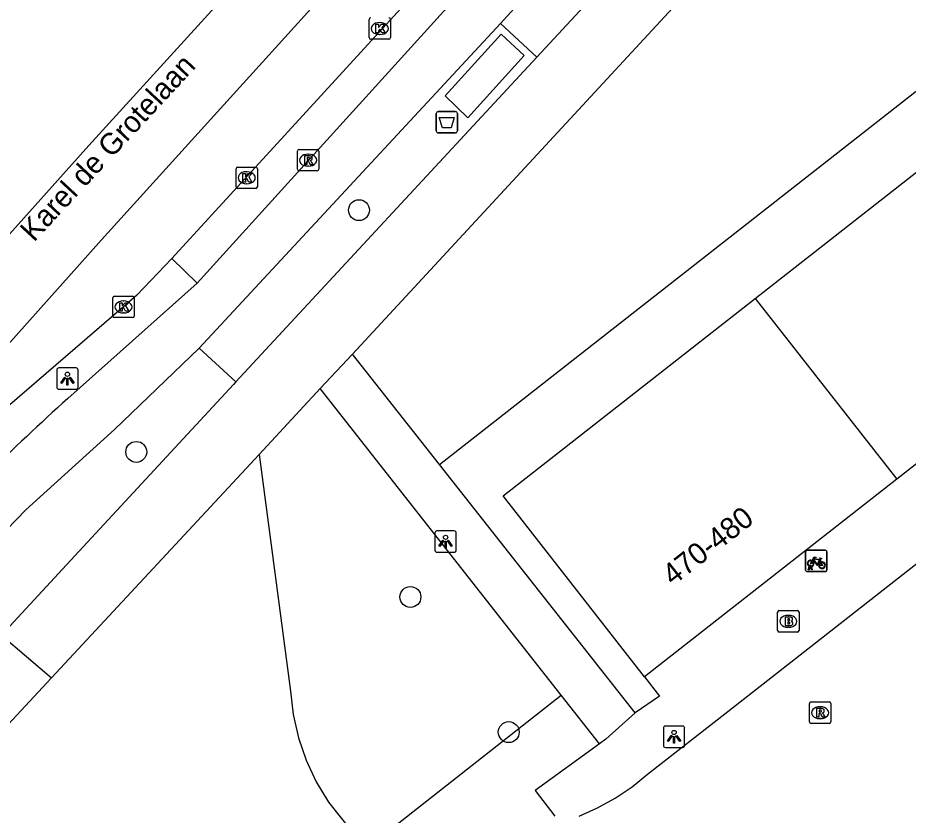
# Model space of a CAD drawing. Extents: x 159222 to 160346, y 381249 to 382166.
# Drawn here: x 159605.34 to 159647.03, y 381597.22 to 381634.54 of the extents above; entities that cross this region are included whole.
import ezdxf

# ---------------------------------------------------------------- set-up
doc = ezdxf.new("R2010")
doc.units = 0
for name, color, linetype in [('IMGEO_Afvalbak', 7, 'Continuous'), ('IMGEO_Boom', 7, 'Continuous'), ('IMGEO_Brandkraan', 7, 'Continuous'), ('IMGEO_Fietsenrek', 7, 'Continuous'), ('IMGEO_Fietspad_gesloten', 7, 'Continuous'), ('IMGEO_Groenvoorziening', 7, 'Continuous'), ('IMGEO_Kolk', 7, 'Continuous'), ('IMGEO_Lichtpunt', 7, 'Continuous'), ('IMGEO_Openbare_ruimte_label', 7, 'Continuous'), ('IMGEO_OVBaan_gesloten', 7, 'Continuous'), ('IMGEO_Pand', 7, 'Continuous'), ('IMGEO_Pand_nummerreeks', 7, 'Continuous'), ('IMGEO_Rijbaan_lokaal_open', 7, 'Continuous'), ('IMGEO_Rijbaan_regionaal_gesloten', 7, 'Continuous'), ('IMGEO_Rioolput', 7, 'Continuous'), ('IMGEO_Voetpad_gesloten', 7, 'Continuous'), ('IMGEO_Voetpad_open', 7, 'Continuous')]:
    doc.layers.add(name, color=color, linetype=linetype)

msp = doc.modelspace()

# ---------------------------------------------------------------- linework, layer by layer
at = {"layer": 'IMGEO_Afvalbak'}
for p, q in [((159625.031, 381630.153), (159625.821, 381630.153)), ((159625.821, 381630.153), (159625.031, 381630.153)), ((159624.931, 381629.253), (159624.931, 381630.053)), ((159624.931, 381630.053), (159624.931, 381629.253)), ((159625.921, 381630.053), (159625.921, 381629.253)), ((159625.921, 381629.253), (159625.921, 381630.053)), ((159625.821, 381629.153), (159625.031, 381629.153)), ((159625.031, 381629.153), (159625.821, 381629.153))]:
    msp.add_line(p, q, dxfattribs=at)
msp.add_lwpolyline([(159625.074, 381629.867), (159625.778, 381629.867), (159625.629, 381629.397), (159625.223, 381629.397), (159625.074, 381629.867)], dxfattribs=at)
for centre, start, end in [((159625.031, 381630.053), 90, 180), ((159625.031, 381630.053), 90, 180), ((159625.821, 381630.053), 0, 90), ((159625.821, 381630.053), 360, 90), ((159625.031, 381629.253), 180, 270), ((159625.031, 381629.253), 180, 270), ((159625.821, 381629.253), 270, 0), ((159625.821, 381629.253), 270, 0)]:
    msp.add_arc(centre, 0.1, start, end, dxfattribs=at)
at = {"layer": 'IMGEO_Boom'}
for centre in [(159621.315, 381625.537), (159610.887, 381614.222), (159623.723, 381607.432), (159628.329, 381601.108)]:
    msp.add_circle(centre, 0.489, dxfattribs=at)
at = {"layer": 'IMGEO_Brandkraan'}
for p, q in [((159640.919, 381605.866), (159640.919, 381606.718)), ((159640.994, 381606.792), (159641.846, 381606.792)), ((159641.92, 381606.718), (159641.92, 381605.866)), ((159641.407, 381606.572), (159641.432, 381606.572)), ((159641.43, 381606.012), (159641.405, 381606.012)), ((159641.846, 381605.792), (159640.994, 381605.792))]:
    msp.add_line(p, q, dxfattribs=at)
for points in [[(159640.919, 381605.866), (159640.919, 381606.718)], [(159640.994, 381606.792), (159641.846, 381606.792)], [(159641.92, 381606.718), (159641.92, 381605.866)], [(159641.267, 381606.492), (159641.267, 381606.092), (159641.48, 381606.092)], [(159641.498, 381606.492), (159641.267, 381606.492)], [(159641.446, 381606.411), (159641.392, 381606.411), (159641.392, 381606.335)], [(159641.392, 381606.335), (159641.445, 381606.335)], [(159641.454, 381606.259), (159641.392, 381606.259), (159641.392, 381606.178)], [(159641.392, 381606.178), (159641.454, 381606.178)], [(159641.846, 381605.792), (159640.994, 381605.792)]]:
    msp.add_lwpolyline(points, dxfattribs=at)
for centre, radius, start, end in [((159640.996, 381606.716), 0.0765, 91.552, 178.448), ((159640.996, 381606.716), 0.0765, 91.552, 178.448), ((159641.844, 381606.716), 0.0765, 1.552, 88.448), ((159641.844, 381606.716), 0.0765, 1.552, 88.448), ((159641.447, 381606.373), 0.0379, 267.8285, 90.9355), ((159641.502, 381606.347), 0.145, 59.4692, 91.5367), ((159641.527, 381606.394), 0.0922, 285.5137, 58.1501), ((159641.532, 381606.202), 0.105, 301.3115, 78.989), ((159641.455, 381606.218), 0.0404, 269.8759, 90.5077), ((159641.486, 381606.343), 0.251, 268.6676, 293.5347), ((159640.996, 381605.868), 0.0765, 181.552, 268.448), ((159640.996, 381605.868), 0.0765, 181.552, 268.448), ((159641.844, 381605.868), 0.0765, 271.552, 358.448), ((159641.844, 381605.868), 0.0765, 271.552, 358.448)]:
    msp.add_arc(centre, radius, start, end, dxfattribs=at)
for centre, major_axis, ratio, start_param, end_param in [((159641.406, 381606.292), (-0.387, 0.002), 0.722429, 4.712389, 7.853982), ((159641.431, 381606.292), (-0.39, 0.002), 0.717154, 1.570796, 4.712389)]:
    msp.add_ellipse(centre, major_axis=major_axis, ratio=ratio, start_param=start_param, end_param=end_param, dxfattribs=at)
at = {"layer": 'IMGEO_Fietsenrek'}
for p, q in [((159642.228, 381608.692), (159642.228, 381609.533)), ((159642.228, 381609.533), (159642.228, 381608.692)), ((159642.303, 381609.617), (159643.144, 381609.617)), ((159643.144, 381609.617), (159642.303, 381609.617)), ((159643.228, 381609.542), (159643.228, 381608.701)), ((159643.228, 381608.701), (159643.228, 381609.542)), ((159642.355, 381608.701), (159642.394, 381608.861)), ((159642.424, 381608.849), (159642.389, 381608.701)), ((159642.466, 381608.873), (159642.465, 381608.877)), ((159642.507, 381608.701), (159642.473, 381608.843)), ((159642.497, 381608.884), (159642.498, 381608.877)), ((159642.505, 381608.847), (159642.54, 381608.701)), ((159642.915, 381609.166), (159642.951, 381609.071)), ((159643.153, 381608.617), (159642.312, 381608.617)), ((159642.312, 381608.617), (159643.153, 381608.617)), ((159642.389, 381608.701), (159642.355, 381608.701)), ((159642.54, 381608.701), (159642.507, 381608.701))]:
    msp.add_line(p, q, dxfattribs=at)
for points in [[(159642.541, 381609.143), (159642.636, 381609.307), (159642.722, 381609.293), (159642.724, 381609.284), (159642.668, 381609.273), (159642.641, 381609.228), (159642.897, 381609.187)], [(159642.897, 381609.187), (159642.922, 381609.236), (159642.916, 381609.24), (159642.893, 381609.244), (159642.881, 381609.251), (159642.88, 381609.254), (159642.882, 381609.259), (159642.977, 381609.244), (159642.979, 381609.234), (159642.969, 381609.221), (159642.957, 381609.215), (159642.943, 381609.221), (159642.915, 381609.166)], [(159642.562, 381609.091), (159642.51, 381609.001), (159642.47, 381608.976), (159642.471, 381609.023), (159642.526, 381609.117)], [(159642.837, 381608.899), (159642.787, 381608.899), (159642.596, 381609.15), (159642.577, 381609.118)], [(159642.884, 381609.162), (159642.627, 381609.203), (159642.61, 381609.174), (159642.777, 381608.954), (159642.884, 381609.162)], [(159642.932, 381609.064), (159642.902, 381609.141), (159642.793, 381608.923), (159642.836, 381608.923)], [(159642.866, 381608.923), (159642.986, 381608.922), (159642.942, 381609.036)], [(159642.962, 381609.043), (159643.017, 381608.898), (159642.867, 381608.898)]]:
    msp.add_lwpolyline(points, dxfattribs=at)
for centre, radius, start, end in [((159642.306, 381609.539), 0.0779, 92.4484, 184.2845), ((159642.306, 381609.539), 0.0779, 92.4484, 184.2845), ((159643.15, 381609.539), 0.0779, 2.4484, 94.2845), ((159643.15, 381609.539), 0.0779, 2.4484, 94.2845), ((159642.468, 381609.002), 0.159, 62.6766, 242.1369), ((159642.468, 381609.002), 0.129, 63.3192, 238.903), ((159642.448, 381608.873), 0.0499, 12.8025, 158.6934), ((159642.468, 381609.002), 0.159, 253.9967, 271.7867), ((159642.448, 381608.873), 0.0174, 12.8025, 163.4502), ((159642.468, 381609.002), 0.129, 253.415, 269.0204), ((159642.468, 381609.002), 0.129, 283.6043, 43.4302), ((159642.468, 381609.002), 0.159, 283.5766, 46.6042), ((159642.995, 381608.918), 0.159, 113.3408, 178.3217), ((159642.995, 381608.918), 0.159, 187.0065, 105.7708), ((159642.995, 381608.918), 0.129, 113.923, 177.9556), ((159642.995, 381608.918), 0.129, 188.6715, 104.5883), ((159642.306, 381608.695), 0.0779, 182.4484, 274.2845), ((159642.306, 381608.695), 0.0779, 182.4484, 274.2845), ((159643.15, 381608.695), 0.0779, 272.4484, 4.2845), ((159643.15, 381608.695), 0.0779, 272.4484, 4.2845)]:
    msp.add_arc(centre, radius, start, end, dxfattribs=at)
at = {"layer": 'IMGEO_Fietspad_gesloten'}
for points in [[(159627.95, 381634.279), (159632.567, 381639.362), (159637.494, 381645.52), (159642.695, 381651.795), (159649.844, 381659.632), (159712.278, 381726.997), (159749.294, 381767.255), (159766.48, 381785.868)], [(159629.68, 381639.699), (159613.744, 381622.115)], [(159627.95, 381634.279), (159613.837, 381619.072)], [(159613.744, 381622.115), (159607.679, 381616.725)], [(159602.096, 381607.781), (159605.72, 381611.514), (159609.864, 381615.275), (159613.837, 381619.072)]]:
    msp.add_lwpolyline(points, dxfattribs=at)
msp.add_arc((159701.931, 381512.769), 140.322, 132.19716, 136.47098, dxfattribs=at)
at = {"layer": 'IMGEO_Groenvoorziening'}
for points in [[(159625.084, 381613.639), (159671.617, 381650.084)], [(159616.639, 381614.101), (159618.108, 381603.028), (159618.241, 381601.924), (159618.489, 381600.841), (159618.848, 381599.789), (159619.316, 381598.78), (159619.886, 381597.826), (159620.974, 381596.463), (159621.716, 381595.714)], [(159621.716, 381595.714), (159630.786, 381602.842)]]:
    msp.add_lwpolyline(points, dxfattribs=at)
at = {"layer": 'IMGEO_Kolk'}
for p, q in [((159621.789, 381633.612), (159621.789, 381634.464)), ((159622.277, 381634.318), (159622.302, 381634.318)), ((159622.79, 381634.464), (159622.79, 381633.612)), ((159622.716, 381633.538), (159621.864, 381633.538)), ((159622.3, 381633.758), (159622.275, 381633.758)), ((159615.558, 381626.626), (159615.558, 381627.478)), ((159615.633, 381627.552), (159616.485, 381627.552)), ((159616.046, 381627.332), (159616.071, 381627.332)), ((159616.559, 381627.478), (159616.559, 381626.626)), ((159616.069, 381626.772), (159616.044, 381626.772)), ((159616.485, 381626.552), (159615.633, 381626.552)), ((159609.789, 381620.58), (159609.789, 381621.432)), ((159609.864, 381621.506), (159610.716, 381621.506)), ((159610.79, 381621.432), (159610.79, 381620.58)), ((159610.277, 381621.286), (159610.302, 381621.286)), ((159610.716, 381620.506), (159609.864, 381620.506)), ((159610.3, 381620.726), (159610.275, 381620.726))]:
    msp.add_line(p, q, dxfattribs=at)
for points in [[(159621.789, 381633.612), (159621.789, 381634.464)], [(159622.11, 381634.238), (159622.233, 381634.238), (159622.233, 381634.087), (159622.363, 381634.238), (159622.527, 381634.238), (159622.381, 381634.087), (159622.534, 381633.838), (159622.382, 381633.838), (159622.297, 381634.002), (159622.233, 381633.935), (159622.233, 381633.838), (159622.11, 381633.838), (159622.11, 381634.238)], [(159622.79, 381634.464), (159622.79, 381633.612)], [(159622.716, 381633.538), (159621.864, 381633.538)], [(159615.558, 381626.626), (159615.558, 381627.478)], [(159615.633, 381627.552), (159616.485, 381627.552)], [(159615.879, 381627.252), (159616.002, 381627.252), (159616.002, 381627.101), (159616.132, 381627.252), (159616.296, 381627.252), (159616.15, 381627.101), (159616.303, 381626.852), (159616.151, 381626.852), (159616.066, 381627.016), (159616.002, 381626.949), (159616.002, 381626.852), (159615.879, 381626.852), (159615.879, 381627.252)], [(159616.559, 381627.478), (159616.559, 381626.626)], [(159616.485, 381626.552), (159615.633, 381626.552)], [(159609.789, 381620.58), (159609.789, 381621.432)], [(159609.864, 381621.506), (159610.716, 381621.506)], [(159610.79, 381621.432), (159610.79, 381620.58)], [(159610.11, 381621.206), (159610.233, 381621.206), (159610.233, 381621.055), (159610.363, 381621.206), (159610.527, 381621.206), (159610.381, 381621.055), (159610.534, 381620.806), (159610.382, 381620.806), (159610.297, 381620.97), (159610.233, 381620.903), (159610.233, 381620.806), (159610.11, 381620.806), (159610.11, 381621.206)], [(159610.716, 381620.506), (159609.864, 381620.506)]]:
    msp.add_lwpolyline(points, dxfattribs=at)
for centre, start, end in [((159621.866, 381634.462), 91.552, 178.448), ((159621.866, 381634.462), 91.552, 178.448), ((159622.714, 381634.462), 1.552, 88.448), ((159622.714, 381634.462), 1.552, 88.448), ((159621.866, 381633.614), 181.552, 268.448), ((159621.866, 381633.614), 181.552, 268.448), ((159622.714, 381633.614), 271.552, 358.448), ((159622.714, 381633.614), 271.552, 358.448), ((159615.635, 381627.476), 91.552, 178.448), ((159615.635, 381627.476), 91.552, 178.448), ((159616.483, 381627.476), 1.552, 88.448), ((159616.483, 381627.476), 1.552, 88.448), ((159615.635, 381626.628), 181.552, 268.448), ((159615.635, 381626.628), 181.552, 268.448), ((159616.483, 381626.628), 271.552, 358.448), ((159616.483, 381626.628), 271.552, 358.448), ((159609.866, 381621.43), 91.552, 178.448), ((159609.866, 381621.43), 91.552, 178.448), ((159610.714, 381621.43), 1.552, 88.448), ((159610.714, 381621.43), 1.552, 88.448), ((159609.866, 381620.582), 181.552, 268.448), ((159609.866, 381620.582), 181.552, 268.448), ((159610.714, 381620.582), 271.552, 358.448), ((159610.714, 381620.582), 271.552, 358.448)]:
    msp.add_arc(centre, 0.0765, start, end, dxfattribs=at)
for centre, major_axis, ratio, start_param, end_param in [((159622.276, 381634.038), (-0.387, 0.002), 0.722429, 4.712389, 7.853982), ((159622.301, 381634.038), (-0.39, 0.002), 0.717154, 1.570796, 4.712389), ((159616.045, 381627.052), (-0.387, 0.002), 0.722429, 4.712389, 7.853982), ((159616.07, 381627.052), (-0.39, 0.002), 0.717154, 1.570796, 4.712389), ((159610.276, 381621.006), (-0.387, 0.002), 0.722429, 4.712389, 7.853982), ((159610.301, 381621.006), (-0.39, 0.002), 0.717154, 1.570796, 4.712389)]:
    msp.add_ellipse(centre, major_axis=major_axis, ratio=ratio, start_param=start_param, end_param=end_param, dxfattribs=at)
at = {"layer": 'IMGEO_Lichtpunt'}
for p, q in [((159607.165, 381618.057), (159607.165, 381617.25)), ((159607.165, 381618.057), (159607.165, 381617.25)), ((159608.067, 381618.152), (159607.259, 381618.152)), ((159608.067, 381618.152), (159607.259, 381618.152)), ((159608.161, 381617.25), (159608.161, 381618.057)), ((159608.161, 381617.25), (159608.161, 381618.057)), ((159607.259, 381617.156), (159608.067, 381617.156)), ((159607.259, 381617.156), (159608.067, 381617.156)), ((159625.775, 381610.522), (159624.967, 381610.522)), ((159625.775, 381610.522), (159624.967, 381610.522)), ((159624.873, 381610.427), (159624.873, 381609.62)), ((159624.873, 381610.427), (159624.873, 381609.62)), ((159625.869, 381609.62), (159625.869, 381610.427)), ((159625.869, 381609.62), (159625.869, 381610.427)), ((159624.967, 381609.526), (159625.775, 381609.526)), ((159624.967, 381609.526), (159625.775, 381609.526)), ((159635.57, 381601.293), (159635.57, 381600.486)), ((159635.57, 381601.293), (159635.57, 381600.486)), ((159636.472, 381601.388), (159635.664, 381601.388)), ((159636.472, 381601.388), (159635.664, 381601.388)), ((159636.566, 381600.486), (159636.566, 381601.293)), ((159636.566, 381600.486), (159636.566, 381601.293)), ((159635.664, 381600.392), (159636.472, 381600.392)), ((159635.664, 381600.392), (159636.472, 381600.392))]:
    msp.add_line(p, q, dxfattribs=at)
for points in [[(159607.539, 381617.721), (159607.578, 381617.693), (159607.39, 381617.431), (159607.352, 381617.458), (159607.539, 381617.721)], [(159607.641, 381617.673), (159607.688, 381617.673), (159607.688, 381617.351), (159607.641, 381617.351), (159607.641, 381617.673)], [(159607.751, 381617.693), (159607.789, 381617.72), (159607.976, 381617.458), (159607.937, 381617.43), (159607.751, 381617.693)], [(159625.247, 381610.091), (159625.286, 381610.063), (159625.098, 381609.801), (159625.06, 381609.828), (159625.247, 381610.091)], [(159625.349, 381610.043), (159625.396, 381610.043), (159625.396, 381609.721), (159625.349, 381609.721), (159625.349, 381610.043)], [(159625.459, 381610.063), (159625.497, 381610.09), (159625.684, 381609.828), (159625.645, 381609.8), (159625.459, 381610.063)], [(159635.944, 381600.957), (159635.983, 381600.929), (159635.795, 381600.667), (159635.757, 381600.694), (159635.944, 381600.957)], [(159636.046, 381600.909), (159636.093, 381600.909), (159636.093, 381600.587), (159636.046, 381600.587), (159636.046, 381600.909)], [(159636.156, 381600.929), (159636.194, 381600.956), (159636.381, 381600.694), (159636.342, 381600.666), (159636.156, 381600.929)]]:
    msp.add_lwpolyline(points, dxfattribs=at)
for centre in [(159607.664, 381617.855), (159625.372, 381610.225), (159636.069, 381601.091)]:
    msp.add_circle(centre, 0.0994, dxfattribs=at)
for centre, start, end in [((159607.259, 381618.057), 90, 180), ((159607.259, 381618.057), 90, 180), ((159608.067, 381618.057), 0, 90), ((159608.067, 381618.057), 0, 90), ((159607.259, 381617.25), 180, 270), ((159607.259, 381617.25), 180, 270), ((159608.067, 381617.25), 270, 0), ((159608.067, 381617.25), 270, 360), ((159624.967, 381610.427), 90, 180), ((159624.967, 381610.427), 90, 180), ((159625.775, 381610.427), 0, 90), ((159625.775, 381610.427), 0, 90), ((159624.967, 381609.62), 180, 270), ((159624.967, 381609.62), 180, 270), ((159625.775, 381609.62), 270, 0), ((159625.775, 381609.62), 270, 360), ((159635.664, 381601.293), 90, 180), ((159635.664, 381601.293), 90, 180), ((159636.472, 381601.293), 0, 90), ((159636.472, 381601.293), 0, 90), ((159635.664, 381600.486), 180, 270), ((159635.664, 381600.486), 180, 270), ((159636.472, 381600.486), 270, 0), ((159636.472, 381600.486), 270, 360)]:
    msp.add_arc(centre, 0.0946, start, end, dxfattribs=at)
at = {"layer": 'IMGEO_OVBaan_gesloten'}
for points in [[(159594.598, 381607.362), (159597.899, 381611.433), (159609.251, 381624.142), (159621.007, 381637.121), (159637.399, 381654.559)], [(159628.555, 381640.744), (159612.549, 381623.266)], [(159612.549, 381623.266), (159610.908, 381621.552), (159610.29, 381621.006), (159598.499, 381610.865), (159596.374, 381609.038), (159594.883, 381607.659), (159594.598, 381607.362)]]:
    msp.add_lwpolyline(points, dxfattribs=at)
at = {"layer": 'IMGEO_Pand'}
for points in [[(159639.869, 381621.408), (159651.678, 381630.657)], [(159658.311, 381622.189), (159646.502, 381612.939)], [(159634.693, 381603.69), (159628.06, 381612.159), (159639.869, 381621.408)], [(159639.869, 381621.408), (159646.502, 381612.939)], [(159646.502, 381612.939), (159634.693, 381603.69)]]:
    msp.add_lwpolyline(points, dxfattribs=at)
at = {"layer": 'IMGEO_Rijbaan_lokaal_open'}
msp.add_lwpolyline([(159631.625, 381597.172), (159632.49, 381597.556), (159633.318, 381598.016), (159634.101, 381598.548), (159634.829, 381599.144), (159638.593, 381602.067), (159674.232, 381629.981)], dxfattribs=at)
at = {"layer": 'IMGEO_Rijbaan_regionaal_gesloten'}
msp.add_lwpolyline([(159562.441, 381576.704), (159564.486, 381578.965), (159572.242, 381587.735), (159595.596, 381613.987), (159600.842, 381619.836), (159608.673, 381628.559), (159619.179, 381640.116), (159632.439, 381654.477), (159662.487, 381686.935), (159673.411, 381698.738), (159692.515, 381719.406), (159697.924, 381725.313), (159711.603, 381740.093), (159741.608, 381772.601), (159749.78, 381781.446), (159760.686, 381793.237), (159777.035, 381810.935), (159791.265, 381826.348), (159802.521, 381838.469), (159810.756, 381847.255), (159814.994, 381851.76)], dxfattribs=at)
at = {"layer": 'IMGEO_Rioolput'}
for p, q in [((159618.433, 381627.451), (159618.433, 381628.303)), ((159618.508, 381628.377), (159619.36, 381628.377)), ((159618.921, 381628.157), (159618.946, 381628.157)), ((159619.434, 381628.303), (159619.434, 381627.451)), ((159618.944, 381627.597), (159618.919, 381627.597)), ((159619.36, 381627.377), (159618.508, 381627.377)), ((159642.408, 381601.591), (159642.408, 381602.443)), ((159642.483, 381602.517), (159643.335, 381602.517)), ((159642.896, 381602.297), (159642.921, 381602.297)), ((159643.409, 381602.443), (159643.409, 381601.591)), ((159642.919, 381601.737), (159642.894, 381601.737)), ((159643.335, 381601.517), (159642.483, 381601.517))]:
    msp.add_line(p, q, dxfattribs=at)
for points in [[(159618.433, 381627.451), (159618.433, 381628.303)], [(159618.508, 381628.377), (159619.36, 381628.377)], [(159619.022, 381628.075), (159618.77, 381628.077), (159618.77, 381627.677)], [(159618.948, 381627.996), (159618.894, 381627.996), (159618.894, 381627.915)], [(159619.434, 381628.303), (159619.434, 381627.451)], [(159618.77, 381627.677), (159618.894, 381627.677), (159618.894, 381627.839), (159618.905, 381627.839)], [(159618.894, 381627.915), (159618.946, 381627.915)], [(159618.952, 381627.81), (159619.023, 381627.677), (159619.163, 381627.677), (159619.098, 381627.803)], [(159619.36, 381627.377), (159618.508, 381627.377)], [(159642.408, 381601.591), (159642.408, 381602.443)], [(159642.483, 381602.517), (159643.335, 381602.517)], [(159642.997, 381602.215), (159642.745, 381602.217), (159642.745, 381601.817)], [(159642.923, 381602.136), (159642.869, 381602.136), (159642.869, 381602.055)], [(159643.409, 381602.443), (159643.409, 381601.591)], [(159642.745, 381601.817), (159642.869, 381601.817), (159642.869, 381601.979), (159642.88, 381601.979)], [(159642.869, 381602.055), (159642.921, 381602.055)], [(159642.927, 381601.95), (159642.998, 381601.817), (159643.138, 381601.817), (159643.073, 381601.943)], [(159643.335, 381601.517), (159642.483, 381601.517)]]:
    msp.add_lwpolyline(points, dxfattribs=at)
for centre, radius, start, end in [((159618.51, 381628.301), 0.0765, 91.552, 178.448), ((159618.51, 381628.301), 0.0765, 91.552, 178.448), ((159618.954, 381627.9), 0.0964, 77.0061, 93.1865), ((159618.968, 381627.957), 0.0378, 276.6634, 79.6772), ((159619.021, 381627.965), 0.109, 350.3612, 89.416), ((159619.358, 381628.301), 0.0765, 1.552, 88.448), ((159619.358, 381628.301), 0.0765, 1.552, 88.448), ((159618.904, 381627.786), 0.0533, 26.0293, 88.6989), ((159618.93, 381628.104), 0.19, 274.7715, 282.9687), ((159619.019, 381627.965), 0.112, 277.5842, 350.9817), ((159619.003, 381627.75), 0.108, 29.5134, 73.7905), ((159618.51, 381627.453), 0.0765, 181.552, 268.448), ((159618.51, 381627.453), 0.0765, 181.552, 268.448), ((159619.358, 381627.453), 0.0765, 271.552, 358.448), ((159619.358, 381627.453), 0.0765, 271.552, 358.448), ((159642.485, 381602.441), 0.0765, 91.552, 178.448), ((159642.485, 381602.441), 0.0765, 91.552, 178.448), ((159642.929, 381602.04), 0.0964, 77.0061, 93.1865), ((159642.943, 381602.097), 0.0378, 276.6634, 79.6772), ((159642.996, 381602.105), 0.109, 350.3612, 89.416), ((159643.333, 381602.441), 0.0765, 1.552, 88.448), ((159643.333, 381602.441), 0.0765, 1.552, 88.448), ((159642.879, 381601.926), 0.0533, 26.0293, 88.6989), ((159642.905, 381602.244), 0.19, 274.7715, 282.9687), ((159642.994, 381602.105), 0.112, 277.5842, 350.9817), ((159642.978, 381601.89), 0.108, 29.5134, 73.7905), ((159642.485, 381601.593), 0.0765, 181.552, 268.448), ((159642.485, 381601.593), 0.0765, 181.552, 268.448), ((159643.333, 381601.593), 0.0765, 271.552, 358.448), ((159643.333, 381601.593), 0.0765, 271.552, 358.448)]:
    msp.add_arc(centre, radius, start, end, dxfattribs=at)
for centre, major_axis, ratio, start_param, end_param in [((159618.92, 381627.877), (-0.387, 0.002), 0.722429, 4.712389, 7.853982), ((159618.945, 381627.877), (-0.39, 0.002), 0.717154, 1.570796, 4.712389), ((159642.895, 381602.017), (-0.387, 0.002), 0.722429, 4.712389, 7.853982), ((159642.92, 381602.017), (-0.39, 0.002), 0.717154, 1.570796, 4.712389)]:
    msp.add_ellipse(centre, major_axis=major_axis, ratio=ratio, start_param=start_param, end_param=end_param, dxfattribs=at)
at = {"layer": 'IMGEO_Voetpad_gesloten'}
msp.add_lwpolyline([(159625.356, 381630.883), (159626.413, 381629.858), (159629.057, 381632.768), (159627.968, 381633.773), (159625.356, 381630.883)], dxfattribs=at)
at = {"layer": 'IMGEO_Voetpad_open'}
for points in [[(159768.968, 381783.54), (159738.017, 381750), (159653.897, 381658.843), (159629.643, 381632.69)], [(159621.019, 381618.793), (159665.232, 381666.59)], [(159629.643, 381632.69), (159627.95, 381634.279)], [(159629.643, 381632.69), (159615.553, 381617.498)], [(159613.744, 381622.115), (159612.549, 381623.266)], [(159613.837, 381619.072), (159615.553, 381617.498)], [(159619.494, 381617.187), (159621.019, 381618.793)], [(159625.084, 381613.639), (159621.019, 381618.793)], [(159615.553, 381617.498), (159615.445, 381617.382), (159608.003, 381609.357), (159604.58, 381605.65)], [(159616.639, 381614.101), (159619.494, 381617.187)], [(159630.786, 381602.842), (159619.494, 381617.187)], [(159606.917, 381603.647), (159616.639, 381614.101)], [(159634.254, 381602.013), (159625.084, 381613.639)], [(159604.58, 381605.65), (159606.917, 381603.647)], [(159568.625, 381562.589), (159576.221, 381570.71), (159577.717, 381572.249), (159606.917, 381603.647)], [(159634.693, 381603.69), (159635.387, 381602.787), (159634.254, 381602.013)], [(159632.581, 381600.562), (159630.786, 381602.842)], [(159634.254, 381602.013), (159632.879, 381600.779), (159632.581, 381600.562)], [(159632.581, 381600.562), (159629.561, 381598.367), (159630.49, 381597.169)]]:
    msp.add_lwpolyline(points, dxfattribs=at)

# ---------------------------------------------------------------- texts
at = {"layer": 'IMGEO_Openbare_ruimte_label'}
msp.add_text('Karel de Grotelaan', height=1, rotation=47.187, dxfattribs=at).set_placement((159606.092, 381624.012))
at = {"layer": 'IMGEO_Pand_nummerreeks'}
msp.add_text('470-480', height=1, rotation=38.0696, dxfattribs=at).set_placement((159636.016, 381607.927))

doc.saveas('drawing.dxf')
